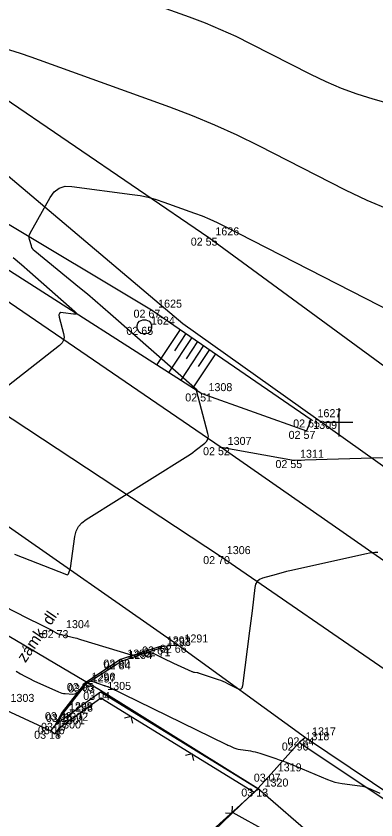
# Model space of a CAD drawing. Extents: x -711234 to -710007, y -1026313 to -1025448.
# Drawn here: x -710586.27 to -710573.7, y -1025538.91 to -1025510.79 of the extents above; entities that cross this region are included whole.
import ezdxf

# ---------------------------------------------------------------- set-up
doc = ezdxf.new("R2010")
doc.units = 0
for name, color, linetype in [('Ex_Major Contours', 7, 'Continuous'), ('Ex_Minor Contours', 7, 'Continuous'), ('Z_body', 7, 'Continuous'), ('Z_body_cisla', 7, 'Continuous'), ('Z_body_vysky_redukovane', 7, 'Continuous'), ('Z_cesta', 7, 'Continuous'), ('Z_hektometricka_sit', 7, 'Continuous'), ('Z_hrany_paty', 7, 'Continuous'), ('Z_katastr_hranice', 7, 'Continuous'), ('Z_komunikace', 7, 'Continuous'), ('Z_komunikace_osa', 7, 'Continuous'), ('Z_obruba', 7, 'Continuous'), ('Z_ploty', 7, 'Continuous'), ('Z_ploty_znacky', 7, 'Continuous'), ('Z_pole_rozhranni', 7, 'Continuous'), ('Z_popisy', 7, 'Continuous'), ('Z_rozhranni', 7, 'Continuous'), ('Z_site_kanalizace_znaky', 7, 'Continuous'), ('Z_technicke_srafy', 7, 'Continuous'), ('Z_vstupy', 7, 'Continuous')]:
    doc.layers.add(name, color=color, linetype=linetype)

# ---------------------------------------------------------------- blocks, each defined once
blk = doc.blocks.new('POINT_DISPLAY')
blk.add_line((0, 0), (0, 0))
blk = doc.blocks.new('Z212')
for p, q in [((-0.17, 0.17), (0, 0)), ((0, 0), (0.17, 0.17))]:
    blk.add_line(p, q)
blk = doc.blocks.new('Z620')
for p, q in [((-0.25, 0.05), (-0.23, 0.13)), ((-0.25, -0.05), (-0.25, 0.05)), ((-0.23, 0.13), (-0.17, 0.2)), ((-0.17, 0.2), (-0.05, 0.25)), ((-0.05, 0.25), (0.05, 0.25)), ((0.05, 0.25), (0.17, 0.2)), ((0.17, 0.2), (0.23, 0.13)), ((0.23, 0.13), (0.25, 0.05)), ((0.25, 0.05), (0.25, -0.05)), ((-0.2, -0.17), (-0.25, -0.05)), ((-0.13, -0.23), (-0.2, -0.17)), ((-0.05, -0.25), (-0.13, -0.23)), ((0.05, -0.25), (-0.05, -0.25)), ((0.13, -0.23), (0.05, -0.25)), ((0.2, -0.17), (0.13, -0.23)), ((0.25, -0.05), (0.2, -0.17))]:
    blk.add_line(p, q)

msp = doc.modelspace()

# ---------------------------------------------------------------- linework, layer by layer
at = {"layer": 'Ex_Major Contours'}
for points in [[(-710562.457, -1025516.901), (-710573.792, -1025513.692), (-710574.352, -1025513.519), (-710574.901, -1025513.318), (-710575.44, -1025513.091), (-710575.968, -1025512.837), (-710578.059, -1025511.767), (-710578.585, -1025511.508), (-710579.119, -1025511.266), (-710579.66, -1025511.041), (-710580.209, -1025510.833), (-710582.829, -1025509.887)], [(-710586.275, -1025533.7), (-710586.123, -1025533.792), (-710585.969, -1025533.88), (-710585.811, -1025533.962), (-710585.651, -1025534.039), (-710584.796, -1025534.431), (-710584.738, -1025534.455), (-710584.678, -1025534.473), (-710584.617, -1025534.485), (-710584.554, -1025534.491), (-710584.294, -1025534.506), (-710584.236, -1025534.503), (-710584.184, -1025534.488), (-710584.137, -1025534.461), (-710584.095, -1025534.422), (-710583.896, -1025534.195), (-710583.876, -1025534.174), (-710583.854, -1025534.155), (-710583.831, -1025534.139), (-710583.805, -1025534.124), (-710583.701, -1025534.069), (-710583.675, -1025534.059), (-710583.649, -1025534.054), (-710583.622, -1025534.055), (-710583.594, -1025534.062), (-710583.198, -1025534.207), (-710583.185, -1025534.211), (-710583.172, -1025534.215), (-710583.159, -1025534.219), (-710583.146, -1025534.223), (-710583.093, -1025534.237), (-710583.08, -1025534.241), (-710583.067, -1025534.246), (-710583.055, -1025534.251), (-710583.042, -1025534.257), (-710578.945, -1025536.256), (-710578.91, -1025536.273), (-710578.875, -1025536.29), (-710578.84, -1025536.306), (-710578.805, -1025536.322), (-710578.665, -1025536.387), (-710578.629, -1025536.401), (-710578.593, -1025536.414), (-710578.556, -1025536.423), (-710578.518, -1025536.43), (-710578.086, -1025536.495), (-710578.002, -1025536.509), (-710577.918, -1025536.527), (-710577.836, -1025536.549), (-710577.754, -1025536.574), (-710577.196, -1025536.761), (-710577.077, -1025536.802), (-710576.958, -1025536.846), (-710576.84, -1025536.891), (-710576.723, -1025536.939), (-710575.388, -1025537.496), (-710575.263, -1025537.544), (-710575.136, -1025537.583), (-710575.006, -1025537.613), (-710574.874, -1025537.634), (-710574.263, -1025537.712), (-710574.17, -1025537.728), (-710574.079, -1025537.75), (-710573.991, -1025537.78), (-710573.904, -1025537.816), (-710573.56, -1025537.975)]]:
    msp.add_lwpolyline(points, dxfattribs=at)
at = {"layer": 'Ex_Minor Contours'}
for points in [[(-710573.223, -1025517.572), (-710574.002, -1025517.243), (-710574.766, -1025516.876), (-710577.79, -1025515.328), (-710578.551, -1025514.953), (-710579.324, -1025514.603), (-710580.106, -1025514.278), (-710580.9, -1025513.977), (-710585.752, -1025512.226), (-710586.121, -1025512.099), (-710586.494, -1025511.985), (-710586.87, -1025511.883), (-710587.25, -1025511.793), (-710588.909, -1025511.428), (-710589.205, -1025511.402), (-710589.463, -1025511.464), (-710589.682, -1025511.614), (-710589.862, -1025511.85), (-710590.505, -1025512.972), (-710590.682, -1025513.199), (-710590.891, -1025513.32), (-710591.132, -1025513.335), (-710591.405, -1025513.243), (-710599.918, -1025508.97)], [(-710586.329, -1025529.617), (-710584.508, -1025530.326), (-710584.486, -1025530.331), (-710584.467, -1025530.328), (-710584.453, -1025530.316), (-710584.441, -1025530.296), (-710584.404, -1025530.199), (-710584.395, -1025530.175), (-710584.388, -1025530.15), (-710584.382, -1025530.125), (-710584.378, -1025530.099), (-710584.216, -1025528.99), (-710584.17, -1025528.808), (-710584.091, -1025528.648), (-710583.976, -1025528.511), (-710583.828, -1025528.396), (-710580.361, -1025526.23), (-710580.272, -1025526.173), (-710580.184, -1025526.113), (-710580.099, -1025526.051), (-710580.014, -1025525.987), (-710579.68, -1025525.725), (-710579.61, -1025525.655), (-710579.568, -1025525.576), (-710579.554, -1025525.487), (-710579.568, -1025525.39), (-710579.972, -1025523.887), (-710579.972, -1025523.884), (-710579.972, -1025523.882), (-710579.97, -1025523.881), (-710579.967, -1025523.881), (-710579.952, -1025523.883), (-710579.95, -1025523.884), (-710579.948, -1025523.883), (-710579.949, -1025523.882), (-710579.951, -1025523.88), (-710582.972, -1025521.218), (-710583.241, -1025520.984), (-710583.511, -1025520.752), (-710583.783, -1025520.523), (-710584.058, -1025520.296), (-710585.619, -1025519.014), (-710585.661, -1025518.975), (-710585.695, -1025518.93), (-710585.722, -1025518.881), (-710585.742, -1025518.827), (-710585.806, -1025518.602), (-710585.816, -1025518.546), (-710585.816, -1025518.491), (-710585.804, -1025518.438), (-710585.781, -1025518.386), (-710585.086, -1025517.131), (-710584.945, -1025516.937), (-710584.77, -1025516.809), (-710584.563, -1025516.745), (-710584.323, -1025516.746), (-710582.214, -1025517.026), (-710581.933, -1025517.07), (-710581.655, -1025517.13), (-710581.381, -1025517.205), (-710581.111, -1025517.294), (-710580.037, -1025517.682), (-710579.771, -1025517.783), (-710579.508, -1025517.892), (-710579.248, -1025518.01), (-710578.992, -1025518.136), (-710573.099, -1025521.153)], [(-710586.373, -1025519.232), (-710586.084, -1025519.48), (-710585.796, -1025519.731), (-710584.22, -1025521.12), (-710584.17, -1025521.172), (-710584.161, -1025521.206), (-710584.192, -1025521.221), (-710584.265, -1025521.217), (-710584.635, -1025521.165), (-710584.713, -1025521.164), (-710584.762, -1025521.19), (-710584.782, -1025521.242), (-710584.772, -1025521.319), (-710584.617, -1025521.897), (-710584.6, -1025522.018), (-710584.617, -1025522.127), (-710584.669, -1025522.225), (-710584.755, -1025522.311), (-710588.435, -1025525.191)], [(-710573.635, -1025529.553), (-710573.733, -1025529.557), (-710573.831, -1025529.566), (-710573.928, -1025529.58), (-710574.025, -1025529.599), (-710576.702, -1025530.196), (-710576.823, -1025530.224), (-710576.944, -1025530.254), (-710577.065, -1025530.285), (-710577.185, -1025530.319), (-710577.664, -1025530.457), (-710577.77, -1025530.503), (-710577.851, -1025530.571), (-710577.905, -1025530.661), (-710577.932, -1025530.774), (-710578.028, -1025531.59), (-710578.049, -1025531.767), (-710578.07, -1025531.944), (-710578.093, -1025532.121), (-710578.116, -1025532.298), (-710578.367, -1025534.221), (-710578.387, -1025534.294), (-710578.424, -1025534.334), (-710578.479, -1025534.341), (-710578.55, -1025534.316), (-710578.87, -1025534.147), (-710578.951, -1025534.106), (-710579.033, -1025534.069), (-710579.116, -1025534.035), (-710579.202, -1025534.005), (-710579.861, -1025533.784), (-710579.883, -1025533.778), (-710579.905, -1025533.772), (-710579.927, -1025533.767), (-710579.949, -1025533.763), (-710580.039, -1025533.75), (-710580.061, -1025533.746), (-710580.083, -1025533.74), (-710580.104, -1025533.733), (-710580.125, -1025533.724), (-710580.759, -1025533.434), (-710580.832, -1025533.401), (-710580.905, -1025533.367), (-710580.977, -1025533.332), (-710581.05, -1025533.297), (-710581.446, -1025533.104), (-710581.465, -1025533.095), (-710581.484, -1025533.087), (-710581.504, -1025533.08), (-710581.524, -1025533.074), (-710581.605, -1025533.053), (-710581.625, -1025533.048), (-710581.645, -1025533.047), (-710581.666, -1025533.048), (-710581.686, -1025533.052), (-710581.925, -1025533.113), (-710581.951, -1025533.119), (-710581.977, -1025533.125), (-710582.004, -1025533.129), (-710582.03, -1025533.134), (-710582.136, -1025533.149), (-710582.162, -1025533.151), (-710582.188, -1025533.15), (-710582.214, -1025533.147), (-710582.24, -1025533.141), (-710584.011, -1025532.604), (-710584.077, -1025532.584), (-710584.142, -1025532.566), (-710584.208, -1025532.549), (-710584.274, -1025532.533), (-710584.652, -1025532.443), (-710584.661, -1025532.441), (-710584.67, -1025532.439), (-710584.679, -1025532.438), (-710584.689, -1025532.437), (-710584.726, -1025532.435), (-710584.735, -1025532.434), (-710584.744, -1025532.432), (-710584.753, -1025532.43), (-710584.762, -1025532.426), (-710584.817, -1025532.401), (-710584.829, -1025532.395), (-710584.84, -1025532.389), (-710584.852, -1025532.383), (-710584.863, -1025532.376), (-710584.943, -1025532.326), (-710584.96, -1025532.315), (-710584.977, -1025532.305), (-710584.995, -1025532.295), (-710585.013, -1025532.286), (-710585.507, -1025532.039), (-710585.595, -1025531.994), (-710585.683, -1025531.95), (-710585.771, -1025531.905), (-710585.859, -1025531.86), (-710587.53, -1025531.006)], [(-710578.699, -1025538.65), (-710577.526, -1025539.297)]]:
    msp.add_lwpolyline(points, dxfattribs=at)
at = {"layer": 'Z_cesta'}
for p, q in [((-710579.11, -1025525.87), (-710576.58, -1025526.32)), ((-710576.58, -1025526.32), (-710571.82, -1025526.18))]:
    msp.add_line(p, q, dxfattribs=at)
at = {"layer": 'Z_hektometricka_sit'}
for p, q in [((-710575, -1025524.5), (-710575, -1025525.5)), ((-710575.5, -1025525), (-710574.5, -1025525))]:
    msp.add_line(p, q, dxfattribs=at)
at = {"layer": 'Z_hrany_paty'}
for p, q in [((-710589.63, -1025516.22), (-710581.54, -1025521.06)), ((-710591.52, -1025516.49), (-710579.78, -1025523.99)), ((-710581.54, -1025521.06), (-710575.96, -1025524.9)), ((-710579.78, -1025523.99), (-710576.12, -1025525.3)), ((-710575.96, -1025524.9), (-710576.12, -1025525.3))]:
    msp.add_line(p, q, dxfattribs=at)
at = {"layer": 'Z_katastr_hranice'}
msp.add_line((-710568.66, -1025545.73), (-710577.81, -1025537.82), dxfattribs=at)
for points in [[(-710600.21, -1025504.82), (-710580.45, -1025521.54), (-710492.86, -1025583.88), (-710429.93, -1025627.5), (-710391.58, -1025654.85), (-710379.57, -1025662.83), (-710367.07, -1025673.36), (-710347.9, -1025691.71), (-710333.8, -1025705.97), (-710271.15, -1025774.38), (-710237.36, -1025811.14)], [(-710577.81, -1025537.82), (-710614.99, -1025571.47), (-710648.25, -1025532.06), (-710620.52, -1025511.94)], [(-710577.81, -1025537.82), (-710583.33, -1025534.38), (-710588.44, -1025531.36), (-710611.74, -1025514.75), (-710620.52, -1025511.94)]]:
    msp.add_lwpolyline(points, dxfattribs=at)
at = {"layer": 'Z_komunikace'}
for p, q in [((-710591.8, -1025517.19), (-710579.11, -1025525.87)), ((-710579.11, -1025525.87), (-710570.39, -1025531.96)), ((-710587.68, -1025527.85), (-710580.62, -1025532.78)), ((-710580.62, -1025532.78), (-710576.16, -1025536.02)), ((-710576.16, -1025536.02), (-710571.17, -1025539.38))]:
    msp.add_line(p, q, dxfattribs=at)
at = {"layer": 'Z_komunikace_osa'}
for p, q in [((-710593.94, -1025519.92), (-710579.13, -1025529.68)), ((-710579.13, -1025529.68), (-710572.26, -1025534.42))]:
    msp.add_line(p, q, dxfattribs=at)
at = {"layer": 'Z_obruba'}
for p, q in [((-710581.23, -1025532.9), (-710581.24, -1025532.84)), ((-710581.23, -1025532.9), (-710582.58, -1025533.36)), ((-710582.58, -1025533.36), (-710583.85, -1025534.17)), ((-710583.85, -1025534.17), (-710584.65, -1025535.2)), ((-710584.65, -1025535.2), (-710584.82, -1025535.51)), ((-710576.16, -1025536.02), (-710576.38, -1025536.2)), ((-710576.38, -1025536.2), (-710571.31, -1025539.58))]:
    msp.add_line(p, q, dxfattribs=at)
at = {"layer": 'Z_ploty'}
for p, q in [((-710584.82, -1025535.51), (-710583.32, -1025534.43)), ((-710583.32, -1025534.43), (-710577.82, -1025537.81)), ((-710584.73, -1025535.66), (-710583.31, -1025534.64)), ((-710583.31, -1025534.64), (-710577.95, -1025537.94)), ((-710585.06, -1025535.79), (-710584.93, -1025535.63)), ((-710584.93, -1025535.63), (-710584.82, -1025535.51)), ((-710585.06, -1025535.79), (-710584.92, -1025535.9)), ((-710584.92, -1025535.9), (-710584.73, -1025535.66)), ((-710577.82, -1025537.81), (-710580.09, -1025539.98))]:
    msp.add_line(p, q, dxfattribs=at)
at = {"layer": 'Z_pole_rozhranni'}
for p, q in [((-710587.55, -1025513.07), (-710579.54, -1025518.54)), ((-710579.54, -1025518.54), (-710570.25, -1025525.35))]:
    msp.add_line(p, q, dxfattribs=at)
at = {"layer": 'Z_rozhranni'}
for p, q in [((-710581.24, -1025532.84), (-710582.62, -1025533.3)), ((-710581.24, -1025532.84), (-710580.62, -1025532.78)), ((-710582.62, -1025533.3), (-710583.87, -1025534.12)), ((-710583.87, -1025534.12), (-710584.66, -1025535.14)), ((-710584.66, -1025535.14), (-710584.93, -1025535.63)), ((-710577.36, -1025537.29), (-710576.38, -1025536.2)), ((-710577.82, -1025537.81), (-710577.36, -1025537.29))]:
    msp.add_line(p, q, dxfattribs=at)
at = {"layer": 'Z_technicke_srafy'}
for p, q in [((-710580.54, -1025521.75), (-710581.36, -1025522.98)), ((-710580.13, -1025522.03), (-710580.94, -1025523.25)), ((-710580.34, -1025521.89), (-710580.74, -1025522.5)), ((-710579.72, -1025522.31), (-710580.52, -1025523.52)), ((-710579.93, -1025522.17), (-710580.33, -1025522.78)), ((-710579.31, -1025522.6), (-710580.1, -1025523.79)), ((-710579.51, -1025522.45), (-710579.91, -1025523.05))]:
    msp.add_line(p, q, dxfattribs=at)
at = {"layer": 'Z_vstupy'}
msp.add_line((-710588.62, -1025534.14), (-710585.06, -1025535.79), dxfattribs=at)

# ---------------------------------------------------------------- block references
at = {"layer": 'Z_body'}
for p in [(-710579.54, -1025518.54), (-710581.54, -1025521.06), (-710581.79, -1025521.66), (-710579.78, -1025523.99), (-710575.96, -1025524.9), (-710576.12, -1025525.3), (-710579.11, -1025525.87), (-710576.58, -1025526.32), (-710579.13, -1025529.68), (-710584.75, -1025532.27), (-710581.24, -1025532.84), (-710580.62, -1025532.78), (-710581.23, -1025532.9), (-710582.62, -1025533.3), (-710582.58, -1025533.36), (-710583.87, -1025534.12), (-710583.85, -1025534.17), (-710583.32, -1025534.43), (-710584.66, -1025535.14), (-710584.65, -1025535.2), (-710584.93, -1025535.63), (-710584.82, -1025535.51), (-710585.06, -1025535.79), (-710576.38, -1025536.2), (-710576.16, -1025536.02), (-710577.36, -1025537.29), (-710577.82, -1025537.81)]:
    msp.add_blockref('POINT_DISPLAY', p, dxfattribs=at)
at = {"layer": 'Z_ploty_znacky'}
for p, rotation in [((-710584.02, -1025535.15), -144.20000000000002), ((-710582.25, -1025535.29), 148.4), ((-710584.83, -1025535.78), -129.10000000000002), ((-710580.12, -1025536.6), 148.4), ((-710578.72, -1025538.67), 43.7)]:
    msp.add_blockref('Z212', p, dxfattribs=dict(at, rotation=rotation))
at = {"layer": 'Z_site_kanalizace_znaky'}
msp.add_blockref('Z620', (-710581.79, -1025521.66), dxfattribs=at)

# ---------------------------------------------------------------- texts
at = {"layer": 'Z_body_cisla'}
for s, p in [('1626', (-710579.31, -1025518.46)), ('1625', (-710581.31, -1025520.99)), ('1624', (-710581.56, -1025521.58)), ('1308', (-710579.55, -1025523.91)), ('1627', (-710575.74, -1025524.82)), ('1309', (-710575.89, -1025525.23)), ('1307', (-710578.88, -1025525.79)), ('1311', (-710576.35, -1025526.24)), ('1306', (-710578.91, -1025529.61)), ('1304', (-710584.53, -1025532.2)), ('1292', (-710581.01, -1025532.77)), ('1293', (-710581, -1025532.82)), ('1291', (-710580.39, -1025532.7)), ('1295', (-710582.39, -1025533.23)), ('1294', (-710582.35, -1025533.28)), ('1296', (-710583.64, -1025534.04)), ('1297', (-710583.63, -1025534.1)), ('1305', (-710583.09, -1025534.36)), ('1303', (-710586.47, -1025534.78)), ('1299', (-710584.43, -1025535.07)), ('1298', (-710584.42, -1025535.12)), ('1301', (-710584.71, -1025535.56)), ('1302', (-710584.59, -1025535.44)), ('1300', (-710584.84, -1025535.71)), ('1318', (-710576.16, -1025536.12)), ('1317', (-710575.93, -1025535.95)), ('1319', (-710577.13, -1025537.21)), ('1320', (-710577.59, -1025537.74))]:
    msp.add_text(s, height=0.28, dxfattribs=at).set_placement(p)
at = {"layer": 'Z_body_vysky_redukovane'}
for s, p in [('02 55', (-710580.17, -1025518.82)), ('02 67', (-710582.17, -1025521.34)), ('02 65', (-710582.42, -1025521.94)), ('02 51', (-710580.363, -1025524.27)), ('02 65', (-710576.59, -1025525.18)), ('02 57', (-710576.75, -1025525.58)), ('02 52', (-710579.74, -1025526.15)), ('02 55', (-710577.21, -1025526.6)), ('02 70', (-710579.737, -1025529.96)), ('02 73', (-710585.38, -1025532.55)), ('02 64', (-710581.87, -1025533.12)), ('02 66', (-710581.25, -1025533.06)), ('02 71', (-710581.813, -1025533.18)), ('02 80', (-710583.227, -1025533.58)), ('02 84', (-710583.21, -1025533.64)), ('02 95', (-710584.5, -1025534.4)), ('03 03', (-710584.457, -1025534.45)), ('03 04', (-710583.927, -1025534.71)), ('03 08', (-710585.267, -1025535.42)), ('03 14', (-710585.233, -1025535.48)), ('03 16', (-710585.513, -1025535.91)), ('03 17', (-710585.403, -1025535.79)), ('03 18', (-710585.643, -1025536.07)), ('02 90', (-710576.987, -1025536.48)), ('02 84', (-710576.79, -1025536.3)), ('03 07', (-710577.967, -1025537.57)), ('03 13', (-710578.403, -1025538.09))]:
    msp.add_text(s, height=0.28, dxfattribs=at).set_placement(p)
at = {"layer": 'Z_popisy'}
msp.add_text('zámk. dl.', height=0.4, rotation=55.8, dxfattribs=at).set_placement((-710585.95, -1025533.43))

doc.saveas('drawing.dxf')
